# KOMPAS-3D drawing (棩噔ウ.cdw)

Views: Вид 7, Вид 6, Вид 5, Вид 4, Вид 3, Вид 2, Вид 1, Выносной элемент В, Выносной элемент, Выносной элемент Г, Выносной элемент Д, Выносной элемент Е
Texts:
  ТМ-27А. КП.
  Первичный вал
  Dance for life
  Текст на чертеже
  Размерные надписи
  Шероховатость
  Линия-выноска #1
  Линия-выноска #2
  Линия-выноска #3
  Отклонения формы и база
  Заголовок таблицы
  Ячейка таблицы
  Стрелка вида
  Обозначение изменения
  Фигурная скобка
  Номер узла
  Марка координационной оси
  VRCB
  Выносная надпись
  Обозначение узла
  Марка/позиционное обозначение с линией-выноской
  Марка/позиционное обозначение на линии
  Марка/позиционное обозначение без линии-выноски
  Rz 40
  Rz 20
  Ra 1,25
  ГОСТ 14034-74
  min
  max
  d-10x82x92x12 ГОСТ 1139-801
  1  Шлицы контролировать по элементам и комплексным калибрам,
  обеспечиваючим указаные размеры и взаимозаменяемость деталей в
  сопряжении;
  2  Поверхность зубьев калить ТВЧ h 1,0...1,5, 51 HRC;
  3 Неуказаные предельные отклонения размеров: по h14, Н14;
  остальные -  IT14 2 .
  Rz 80
  Сталь 45 ГОСТ 1050-88
  НТУ ХПИ
  Каф АиТ
  Павлий
  ТМ-27А. КП.-
Dimensions and other numbers on the sheet: 7; 48; 2; 5; 3; 327,5; 96; 32,5; 68; 53; 47; 10; 54; 4; 0,02; 14; 2 отв. центровочных С8; 65; 60; 50; 2 фаски; 62; 2,5; 3,5; 52,2; 56; 0,05/100; 0,5; 12; 92; 82; 77,1; 1:1; 1; 0; 6; 8; 9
